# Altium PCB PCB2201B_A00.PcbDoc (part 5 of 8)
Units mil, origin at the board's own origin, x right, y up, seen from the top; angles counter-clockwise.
Board outline 4523.63 x 2358.23 mil, 6 copper layers (Top Layer, Signal Layer 2, Signal Layer 3, Signal Layer 4, Signal Layer 5, Bottom Layer), stack 61.221 mil thick; 383 components, 308 nets, 1386 pads, 1147 vias.
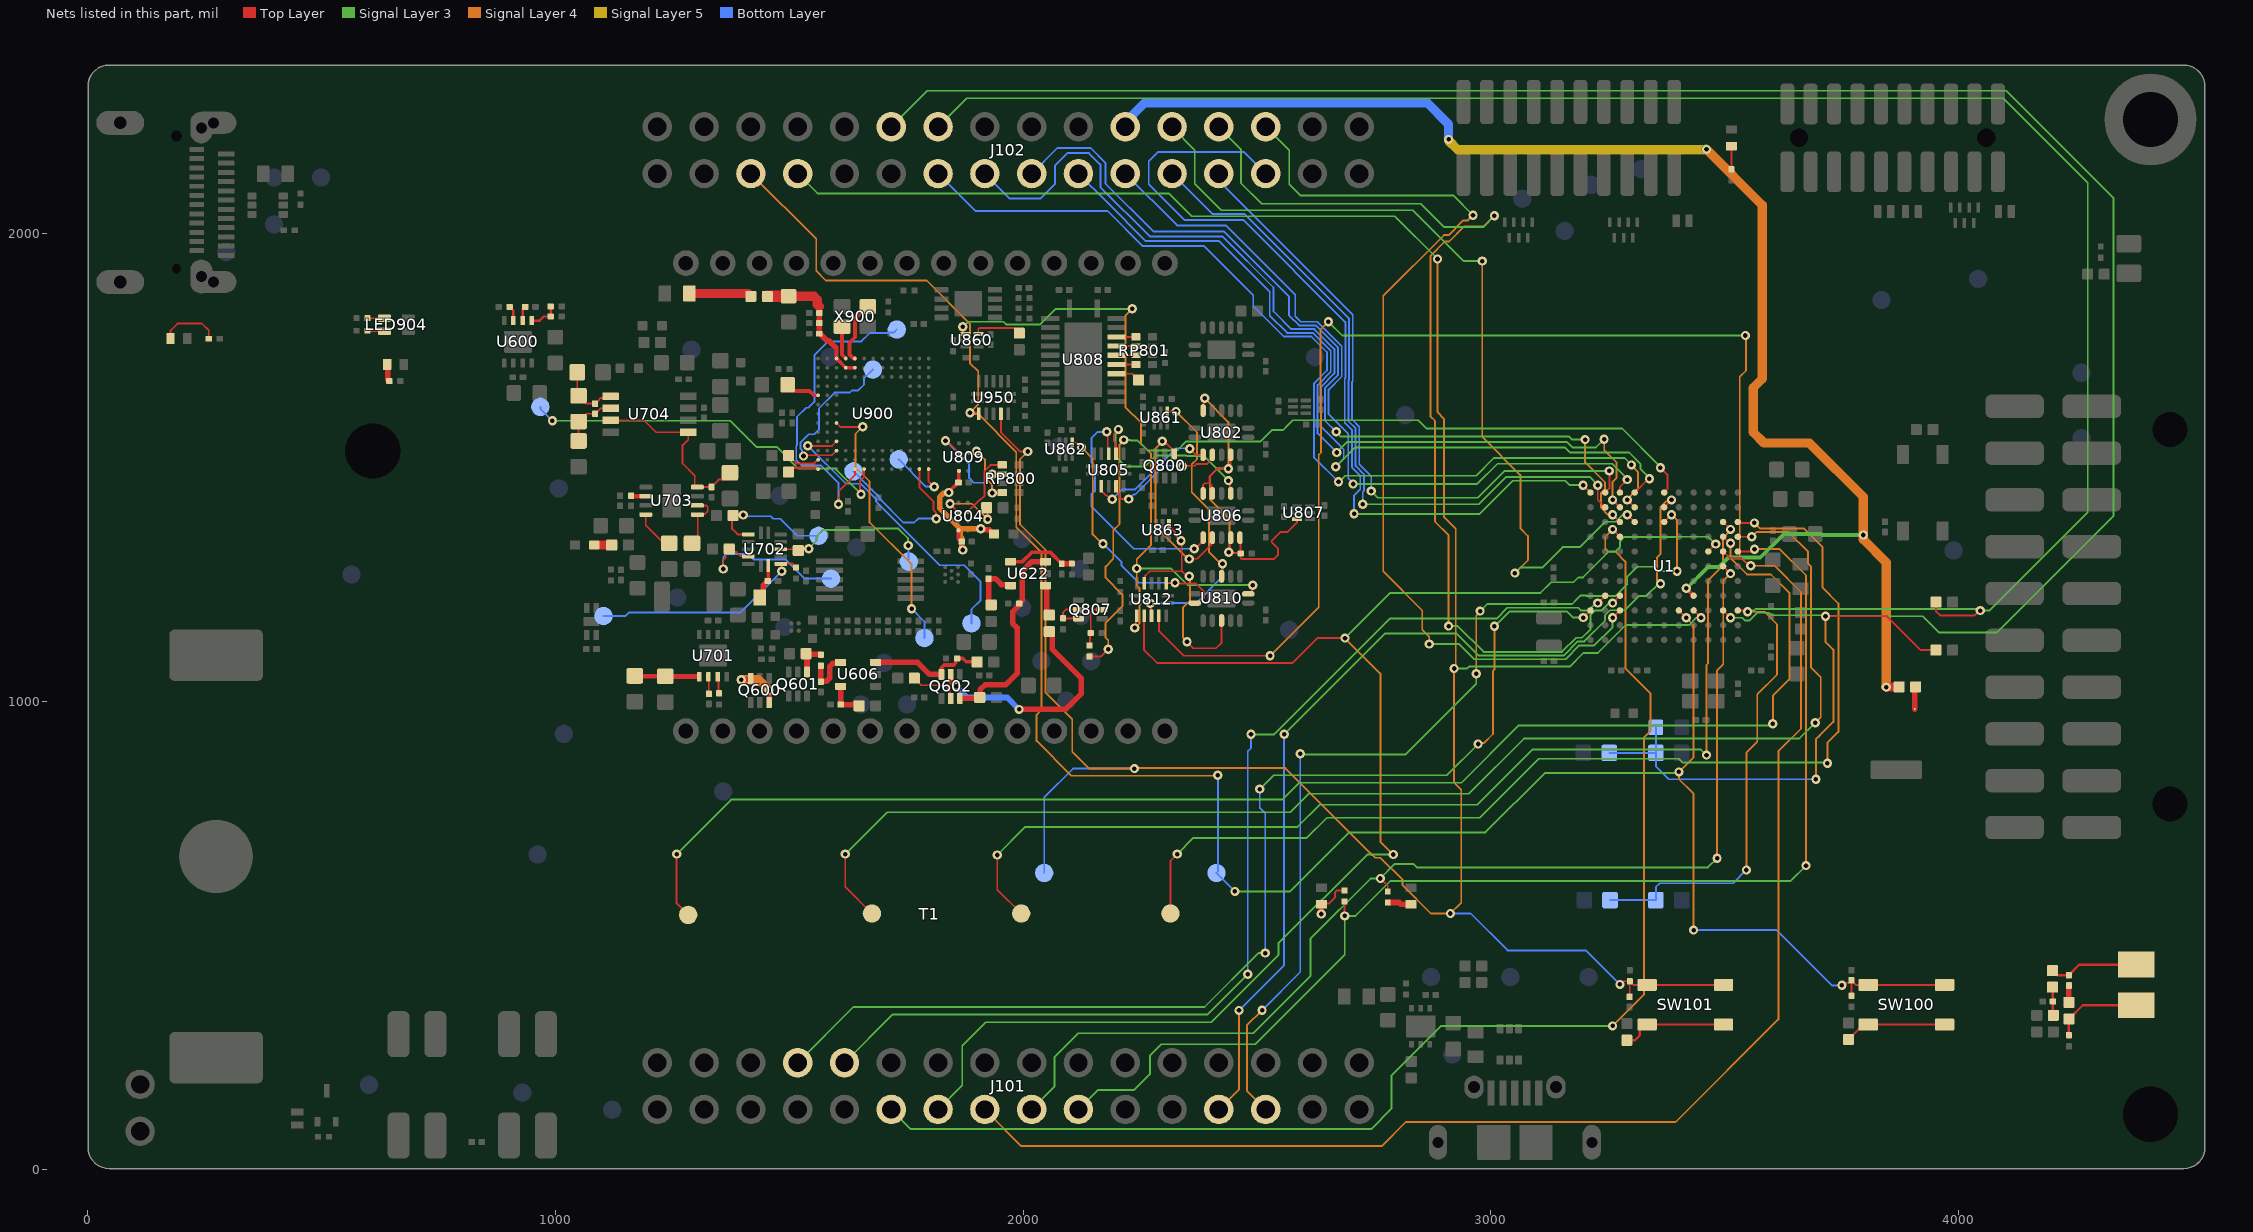
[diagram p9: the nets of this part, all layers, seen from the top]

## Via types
v1: diameter 19.68, hole 9.84, Top Layer to Bottom Layer, tented both sides, 768 vias
v2: diameter 20, hole 9.84, Top Layer to Bottom Layer, tented both sides, 379 vias

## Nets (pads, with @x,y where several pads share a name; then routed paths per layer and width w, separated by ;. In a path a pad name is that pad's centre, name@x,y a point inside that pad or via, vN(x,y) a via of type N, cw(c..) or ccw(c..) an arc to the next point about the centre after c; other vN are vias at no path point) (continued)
MCU_PB9: C102.1 J102.5 R100.1 SW100.3 SW100.4 TPJ652.1 U1.J7 U950.8 | length 4733
  Top Layer w3.94: v2(1886.66,1617.66) 1903.54,1617.66 1905.51,1615.69 U950.8@1905.51,1614.76 ; U1.J7@3401.57,1194.88 v1(3417.35,1179.09) ; v1(3750,393.7) 3754.26,393.7 3759.89,399.33 3766.1,399.33 C102.1@3770.43,403.66 ; C102.1@3770.36,404.52 C102.1@3770.43,404.45 C102.1@3770.43,403.66 ; R100.1@3770.43,371.46 C102.1@3770.43,403.66 ; SW100.3@3969.49,394.6 SW100.4@3806.1,394.6 3779.5,394.6 C102.1@3770.43,403.66
  Signal Layer 3 w3.94: J102.5@1418.5,2128.43 J102.5@1419.53,2128.43 ; v1(2452.76,594.49) 2570.87,594.49 2696.85,720.47 2988.19,720.47 3114.96,847.24 3398.97,847.24 v1(3401.53,849.81)
  Signal Layer 4 w3.94: J102.5@1418.5,2128.43 1558.07,1988.86 1558.07,1920.73 1578.89,1899.91 1794.4,1899.91 1886.63,1807.68 1886.63,1723.38 1904.29,1705.73 1904.29,1635.28 v2(1886.66,1617.66) ; v2@1885.73,1616.73 1887.51,1614.95 1903.9,1614.95 1985.62,1533.23 1985.62,1372.64 2039.37,1318.9 2039.37,982.28 2028.9,971.81 2028.9,915.98 2103.35,841.54 2415.35,841.54 v1(2416.34,842.52) ; v1(3417.35,1179.09) 3432.66,1163.79 3432.66,879.99 3402.47,849.81 v1(3401.53,849.81) 3401.53,834.69 3433.07,803.15 v1(3433.07,511.81)
  Bottom Layer w3.94: v1(2416.34,842.52) 2416.34,636.81 TPJ652.1@2413.39,633.86 v1(2452.76,594.49) ; v1(3433.07,511.81) 3610.47,511.81 3728.58,393.7 v1(3750,393.7)
MCU_PB10: C103.1 J102.7 R101.1 SW101.3 SW101.4 TPJ653.1 U1.J8 U950.11 | length 6302.6
  Top Layer w3.94: U950.11@1952.76,1614.76 1952.76,1575.56 1993.87,1534.45 v2(2009.84,1534.45) ; v1(3275.59,395.67) 3278.44,395.67 3285.17,402.4 R101.1@3296.69,402.4 ; C103.1@3296.34,369.06 3296.52,369.23 3296.52,402.22 R101.1@3296.69,402.4 ; U1.J8@3433.07,1194.88 v1(3448.85,1179.09) ; SW101.3@3497.05,394.6 SW101.4@3333.66,394.6 3304.1,394.6 3296.69,402.01 R101.1@3296.69,402.4
  Signal Layer 3 w3.94: J102.7@1518.5,2128.43 1560.75,2086.18 2311.46,2086.18 2360.24,2037.4 2794.29,2037.4 v1(2885.83,1945.87) ; v1(2921.26,1070.87) 2949.26,1070.87 2953.19,1074.8 3168.31,1074.8 3197.41,1103.91 3228.61,1103.91 3288.49,1163.78 3423.69,1163.78 3439,1179.09 v1(3448.85,1179.09)
  Signal Layer 4 w3.94: v2(2009.84,1534.45) 1993.5,1518.11 1993.5,1378.77 2048.23,1324.04 2048.23,1019.46 2105.32,962.38 2105.32,892.72 2141.19,856.85 v1(2238.06,856.85) 2239.05,857.83 2560.78,857.83 2742.28,676.34 2752.28,666.34 2763.78,666.34 2811.02,619.09 2811.02,607.59 2871.37,547.24 v1(2913.39,547.24) 2936.57,570.43 2936.57,811.7 2921.26,827.02 v1(2921.26,1070.87) 2921.26,1075.13 2924.76,1078.63 2924.76,1369.37 2899.49,1394.65 2899.49,1604.61 2885.83,1618.27 v1(2885.83,1945.87)
  Bottom Layer w3.94: TPJ653.1@2045.28,633.86 2045.28,795.28 2106.85,856.85 v1(2238.06,856.85) ; v1(2913.39,547.24) 2956.69,547.24 3035.43,468.5 3202.76,468.5 v1(3275.59,395.67)
MCU_PB15: J101.11 U1.D3 | length 2864.4
  Top Layer w3.94: v1(3259.89,1368.1) U1.D3@3275.59,1352.36
  Signal Layer 3 w4: J101.11@1718.5,128.43 1760.31,86.61 2744.09,86.61 2787.4,129.92 2787.4,200.79 2893.7,307.09 v1(3259.84,307.09)
  Signal Layer 4 w3.94: v1(3259.89,1368.1) 3244.09,1352.3 3244.09,1326.77 3250.46,1320.41 3266.21,1320.41 3287.4,1299.21 3287.4,1070.87 3341.1,1017.17 3341.1,937.56 3326.77,923.23
  Signal Layer 4 w4: v1(3259.84,307.09) 3260.02,307.09 3326.77,373.84 3326.77,923.23
MCU_PC1: J101.8 U1.J1 | length 2460.5
  Top Layer w3.94: v1(3197.42,1179.67) U1.J1@3212.6,1194.88
  Signal Layer 3 w3.94: J101.8@1518.5,228.43 1637.52,347.44 2387.8,347.44 2502.95,462.6 v1(2517.72,462.6) ; v1(2505.91,812.99) 2535.43,842.52 2905.51,842.52 v1(2972.44,909.45) ; v1(3007.44,1161.16) 3008.02,1161.16 3039.77,1192.91 3162.16,1192.91 3175.41,1179.67 v1(3197.42,1179.67)
  Signal Layer 4 w3.94: v1(2972.44,909.45) 2974.36,911.37 2984.91,911.37 3004.37,930.83 3004.37,1065.83 3007.44,1068.9 v1(3007.44,1161.16)
  Bottom Layer w3.94: v1(2505.91,812.99) 2505.91,773.62 2517.72,761.81 v1(2517.72,462.6)
MCU_PC2: J101.10 U1.H2 | length 2340.6
  Top Layer w3.94: v1(3228.35,1210.59) U1.H2@3244.09,1226.38
  Signal Layer 3 w3.94: J101.10@1618.5,228.43 1721.77,331.69 2394.69,331.69 v1(2480.32,417.32) ; v1(2487.2,930.12) 2536.42,930.12 2783.9,1177.6 3012.03,1177.6 3035.22,1200.79 3186.29,1200.79 3192.1,1194.98 3203.77,1194.98 3204.34,1194.41 3207.93,1194.41 3224.12,1210.59 v1(3228.35,1210.59)
  Bottom Layer w3.94: v1(2480.32,417.32) 2480.32,893.7 2487.2,900.59 v1(2487.2,930.12)
MCU_PC8: T1.1 U1.D10 | length 3106.4
  Top Layer w3.94: v1@1260.83,675.27 1259.84,674.29 v1(1259.84,674.21) 1259.84,568.83 T1.1@1284.42,544.26 ; U1.D10@3496.06,1352.36 3510.83,1337.61 3511.8,1336.64 v1(3511.8,1338.58)
  Signal Layer 3 w3.94: v1(1259.84,674.21) 1376.24,790.61 2554.39,790.61 2590.55,826.77 2937.01,826.77 3059.49,949.25 3598.86,949.25 v1(3602.36,952.76)
  Signal Layer 4 w3.94: v1(3511.8,1338.58) 3511.8,1307.09 3547.24,1271.65 3598.43,1271.65 3637.8,1232.28 3637.8,1047.99 3602.36,1012.56 v1(3602.36,952.76)
MCU_PC9: T1.2 U1.D11 | length 2892.7
  Top Layer w3.94: v1(1620.08,674.21) 1620.08,604.33 T1.2@1677.17,547.24 ; U1.D11@3527.56,1352.36 v1(3557.08,1352.36)
  Signal Layer 3 w3.94: v1(1620.08,674.21) 1709.65,763.78 2570.87,763.78 2610.24,803.15 2952.76,803.15 3070.87,921.26 3659.17,921.26 3692.75,954.85 v1(3692.93,954.85)
  Signal Layer 4 w3.94: v1(3557.08,1352.36) 3566.92,1362.2 3635.63,1362.2 3677.6,1320.23 3677.6,1294.84 3683.55,1288.89 3683.55,1073.7 3704.72,1052.52 3704.72,966.82 3692.93,955.02 v1(3692.93,954.85)
MCU_PC10: T1.3 U1.C10 | length 2286
  Top Layer w3.94: v1(1944.88,672.24) 1944.88,598.43 T1.3@1996.06,547.24 ; U1.C10@3496.06,1383.86 v1(3511.85,1368.09)
  Signal Layer 3 w3.94: v1(1944.88,672.24) 2004.92,732.28 2586.61,732.28 2633.86,779.53 2970.27,779.53 3088.38,897.64 3448.82,897.64 v1(3460.63,885.83)
  Signal Layer 4 w3.94: v1(3460.63,885.83) 3460.63,1078.74 3464.16,1082.27 3464.16,1259.44 3496.06,1291.34 3496.06,1350.57 3511.85,1366.36 v1(3511.85,1368.09)
MCU_PC11: T1.4 U1.C11 | length 2299.7
  Top Layer w3.94: T1.4@2314.96,547.24 2314.96,659.45 v1(2329.72,674.21) ; U1.C11@3527.56,1383.86 3529.53,1381.89 v1(3562.99,1381.89)
  Signal Layer 3 w3.94: v1(2329.72,674.21) 2364.17,708.66 2606.3,708.66 2649.61,751.97 2976.38,751.97 3102.27,877.86 3401.38,877.86 3408.97,870.28 3716.89,870.28 v1(3719.06,868.11)
  Signal Layer 4 w3.94: v1(3562.99,1381.89) 3574.8,1370.08 3668.15,1370.08 3708.6,1329.63 3708.6,1243.52 3742.44,1209.69 3742.44,935.39 3718.91,911.85 3718.91,868.26 v1(3719.06,868.11)
MCU_PD3: C250.1 J102.12 R240.2 R241.1 R245.1 U1.J10 | length 5590.4
  Top Layer w3.94: U1.J10@3496.06,1194.88 v1(3511.85,1179.09) ; v1(3714.8,1182.62) 3846.04,1182.62 3918.43,1110.24 R241.1@3950.79,1110.24
  Signal Layer 3 w3.94: J102.12@1718.5,2228.43 1795.45,2305.37 4101.37,2305.37 4330.71,2076.04 4330.71,1397.64 4080.71,1147.64 3957.8,1147.64 3922.82,1182.62 v1(3714.8,1182.62) ; v1(3511.85,1179.09) 3537.44,1179.09 3543.31,1173.23 3552.03,1173.23 3568.85,1190.06 3593.41,1190.06 3598.93,1184.53 3713.03,1184.53 v1@3714.8,1182.76
  Signal Layer 4 w3.94: v1@3688.63,831.74 3690.94,829.43 3694.2,829.43 v1@3699.92,835.16 ; v1(3694.31,834.12) 3694.31,919.18 ; 3703.68,928.55 3694.31,919.18 ; v1(3714.8,1182.62) 3714.8,1128.19 3731.81,1111.18 3731.81,956.68 3694.31,919.18
  Bottom Layer w3.94: R240.2@3252.68,890.43 R245.1@3352.4,890.43 ; C250.1@3352.4,945 R245.1@3352.4,890.43 ; v1(3694.31,834.12) 3379.93,834.12 3352.4,861.65 R245.1@3352.4,890.43
MCU_PD4: J102.14 R242.1 R243.1 R244.2 U1.J11 | length 5183.4
  Top Layer w3.94: U1.J11@3527.56,1194.88 3545.51,1194.88 v1(3548.4,1191.99) ; R242.1@3950.79,1212.6 3950.79,1193.04 3959.65,1184.17 4033.4,1184.17 4043.67,1194.45 v1(4045.39,1194.45)
  Signal Layer 3 w3.94: J102.14@1818.5,2228.43 1879.45,2289.37 4095.1,2289.37 4275.15,2109.32 4275.15,1405.07 4064.53,1194.45 4041.13,1194.45 4037.65,1197.93 3565.59,1197.93 3562.66,1195 3551.41,1195 v1(3548.4,1191.99)
  Signal Layer 4 w3.94: v1(3545.79,640.28) 3545.79,890.79 3569.17,914.17 3569.17,1015.87 3611.22,1057.92 3611.22,1165.43 3584.66,1191.99 v1(3548.4,1191.99)
  Bottom Layer w3.94: R244.2@3254.45,575.79 R243.1@3352.4,575.79 ; R243.1@3352.32,575.71 R243.1@3352.4,575.79 ; v1(3545.79,640.28) 3517.44,611.93 3360.47,611.93 3352.4,603.86 R243.1@3352.4,575.79
MCU_PD8: J102.22 R246.1 U1.H8 | length 3190.2
  Top Layer w8: v1(3417.35,1242.09) U1.H8@3433.07,1226.38
  Top Layer w19.68: v1(3844.84,1031.1) 3871.65,1031.1 R246.1@3872.05,1031.5
  Signal Layer 3 w8: v1(3417.35,1242.09) 3418.25,1242.09 3463.95,1287.8 3487.54,1287.8 3507.5,1307.76 3575.48,1307.76 3625.98,1358.27 3705.07,1358.27 3707.32,1356.02 v1(3795.55,1356.02)
  Signal Layer 3 w19.68: v1@3459.66,2181.09 v1(3460.63,2180.12)
  Signal Layer 4 w19.68: v1(3460.63,2180.12) 3579.72,2061.02 3579.72,1690.16 3560.32,1670.75 3560.32,1575.76 3583.4,1552.68 3680.43,1552.68 3795.55,1437.56 v1(3795.55,1356.02) 3795.55,1346.73 3844.84,1297.44 v1(3844.84,1031.1)
  Signal Layer 5 w19.68: v1(2909.41,2201.46) 2909.41,2199.29 2929.29,2179.41 3459.92,2179.41 v1(3460.63,2180.12)
  Bottom Layer w19.68: J102.22@2218.5,2228.43 2218.5,2237.83 2260.2,2279.53 2863.94,2279.53 2909.41,2234.06 v1(2909.41,2201.46)
MCU_PD13: J102.24 U1.C4 | length 1861.2
  Top Layer w3.94: v1(3291.35,1399.59) U1.C4@3307.09,1383.86
  Signal Layer 3 w3.94: J102.24@2318.5,2228.43 2318.5,2227.32 2367.13,2178.7 2367.13,2106.3 2423.23,2050.2 2832.68,2050.2 2941.44,1941.44 v1(2981.3,1941.44) ; v1(3051.18,1274.61) 3063.1,1286.53 3083.28,1286.53 3109.3,1286.53 3153.05,1330.27 3189.8,1330.27 3243.81,1384.28 3266.19,1384.28 3281.5,1399.59 v1(3291.35,1399.59)
  Signal Layer 4 w3.94: v1(2981.3,1941.44) 2981.3,1565.94 3062.99,1484.25 3062.99,1370.08 3079.18,1353.89 3079.18,1302.6 v1(3051.18,1274.61) ; v1@3291.35,1397.61 v1(3291.35,1399.59) v1@3291.35,1400.88
MCU_PD14: J102.26 U1.H3 | length 2166.6
  Top Layer w3.94: v1(3259.84,1210.63) U1.H3@3275.59,1226.38
  Signal Layer 3 w3.94: J102.26@2418.5,2228.43 2418.5,2227.32 2465.55,2180.28 2465.55,2108.27 2509.84,2063.98 2850.39,2063.98 2900.15,2014.22 2983.27,2014.22 v1(3007.44,2038.39) ; v1(2909.45,1161.42) 2929.13,1161.42 2984.25,1106.3 3151.57,1106.3 3181.79,1136.51 3194.59,1136.51 3213.04,1154.97 3213.04,1185.44 3222.01,1194.41 3235.24,1194.41 3251.46,1210.63 v1(3259.84,1210.63)
  Signal Layer 4 w3.94: v1(2909.45,1161.42) 2909.45,1355.32 2880.35,1384.41 2880.35,1599.96 2870.52,1609.8 2870.52,1952.21 2901.58,1983.27 2910.43,1983.27 2942.91,2015.75 2984.8,2015.75 v1(3007.44,2038.39)
MCU_PD15: J102.28 U1.J3 | length 2087.8
  Top Layer w3.94: v1(3259.84,1179.13) U1.J3@3275.59,1194.88
  Signal Layer 3 w3.94: J102.28@2518.5,2228.43 2568.9,2178.03 2568.9,2105.32 2592.52,2081.69 2919.29,2081.69 v1(2961.61,2039.37) ; v1(2868.31,1122.87) 2931.99,1122.87 2964.32,1090.55 3159.45,1090.55 3188.98,1120.08 3220.49,1120.08 3259.84,1159.43 v1(3259.84,1179.13)
  Signal Layer 4 w3.94: v1(2868.31,1122.87) 2867.96,1123.22 2867.96,1138.62 2853.07,1153.51 2853.07,1194.8 2769.68,1278.19 2769.68,1867.13 2899.61,1997.05 2909.45,1997.05 2940.94,2028.54 2950.79,2028.54 v1(2961.61,2039.37)
MCU_PE0: J101.13 U1.E9 U812.2 | length 3220.4
  Top Layer w3.94: U812.2@2258.86,1183.66 2258.86,1110.24 2286.36,1082.74 2576.12,1082.74 2629.21,1135.83 2685.04,1135.83 v1@2686.02,1134.84 ; U1.E9@3464.57,1320.87 3464.62,1320.87 v1(3480.35,1336.59)
  Signal Layer 3 w3.94: J101.13@1818.5,128.43 1870.08,180 1870.08,264.76 1920.28,314.96 2402.58,314.96 2545.82,458.2 2545.82,483.26 2735.79,673.23 2760.84,673.23 v1(2791.34,673.23) ; v1(2687.99,1135.83) 2784.45,1232.28 3105.82,1232.28 3128.57,1255.03 3176.42,1255.03 3186.7,1265.31 3196.41,1265.31 3251.97,1320.87 3265.77,1320.87 3276.04,1331.13 3276.04,1342.94 3285.01,1351.91 3393.24,1351.91 3393.7,1352.36 3464.58,1352.36 v1(3480.35,1336.59)
  Signal Layer 4 w3.94: v1(2687.99,1135.83) 2763.78,1060.04 2763.78,700.79 v1(2791.34,673.23)
MCU_PE1: J101.15 U1.E10 U812.4 | length 5447.7
  Top Layer w3.94: U812.4@2290.35,1183.66 2290.35,1151.57 2343.88,1098.05 2526.2,1098.05 v1@2526.57,1098.43 ; U1.E10@3496.06,1320.87 3509.82,1307.09 3535.42,1307.09 3552.09,1290.42 v1(3555.29,1290.42)
  Signal Layer 3 w3.94: v1(2652.56,1812.01) 2682.09,1782.48 v1(3543.74,1782.48)
  Signal Layer 4 w3.94: J101.15@1918.5,128.43 1996.61,50.32 2766.61,50.32 2817.95,101.65 3394.96,101.65 3614.17,320.87 3614.17,893.7 3662.51,942.04 3662.51,1234.14 3606.24,1290.42 v1(3555.29,1290.42) 3552.09,1290.42 3531.5,1311.01 3531.5,1693.9 3545.28,1707.68 3545.28,1782.48 v1(3543.74,1782.48) ; v1(2527.94,1098.05) 2528.28,1098.05 2631.89,1201.65 2631.89,1527.42 2636.82,1532.35 2636.82,1621.53 2635.51,1622.83 2635.51,1794.96 v1(2652.56,1812.01)
MCU_PE2: J101.17 R106.2 U1.F10 | length 2453.8
  Top Layer w3.94: v1(2763.78,622.05) 2779.53,606.3 R106.2@2779.53,594.49 ; U1.F10@3496.06,1289.37 3496.06,1289.31 3511.75,1273.62 v1(3511.81,1273.62)
  Signal Layer 3 w3.94: J101.17@2018.5,128.43 2066.93,176.85 2066.93,240.16 2118.11,291.34 2492.09,291.34 2614.25,413.5 2614.25,493.58 2742.72,622.05 v1(2763.78,622.05) 2794.84,653.11 2834.1,653.11 2841.53,645.67 3463.58,645.67 v1(3483.27,665.35)
  Signal Layer 4 w3.94: v1(3483.27,665.35) 3483.27,1066.93 3496.52,1080.18 3496.52,1258.33 v1(3511.81,1273.62)
MCU_PE3: J101.19 R107.2 U1.E11 | length 2665.9
  Top Layer w3.94: R107.2@2687.01,572.83 2687.28,572.56 2687.28,542.41 v1(2687.56,542.14) ; U1.E11@3527.56,1320.87 3561.02,1320.87 3563.17,1323.01 v1(3563.17,1325.85)
  Signal Layer 3 w3.94: J101.19@2118.5,128.43 2160.43,170.35 2237.28,170.35 2271.65,204.72 2271.65,244.09 2295.28,267.72 2496.06,267.72 2687.56,459.22 v1(2687.56,542.14) 2710.47,542.14 2785.35,617.02 3640.64,617.02 v1(3673.23,649.61)
  Signal Layer 4 w3.94: v1(3563.17,1325.85) 3617.06,1325.85 3673.23,1269.69 v1(3673.23,649.61)
MCU_PE8: J102.13 U1.B4 | length 2075.2
  Top Layer w3.94: v1@3294.12,1428.3 U1.B4@3307.09,1415.35
  Signal Layer 3 w3.94: v1(2674.13,1469.76) 2675.35,1469.76 2688.46,1482.88 2968.22,1482.88 3006.01,1520.67 3285.43,1520.67 v1(3300.2,1505.91)
  Signal Layer 4 w3.94: v1(3291.35,1431.09) 3291.35,1432.65 3314.53,1455.84 3314.53,1490.58 3300.2,1504.92 v1(3300.2,1505.91)
  Bottom Layer w3.94: J102.13@1818.5,2128.43 1898.17,2048.76 2180.57,2048.76 2255.91,1973.43 2387.32,1973.43 2492.13,1868.62 2492.13,1845.47 2557.35,1780.24 2616.18,1780.24 2649.61,1746.82 2649.61,1707.87 2621.5,1679.76 2621.5,1522.4 v1(2674.13,1469.76)
MCU_PE9: J102.15 U1.A4 | length 2130.7
  Top Layer w3.94: U1.A4@3307.09,1446.85 3314.62,1454.42 ; U1.A4@3307.1,1446.85 3336.63,1476.38 v1(3338.58,1476.38)
  Signal Layer 3 w3.94: v1(2668.46,1502.01) 2709.21,1542.76 3158.5,1542.76 3168.53,1532.73 3295.03,1532.73 3319.33,1508.42 3319.33,1497.6 3338.58,1478.35 v1(3338.58,1476.38)
  Bottom Layer w3.94: J102.15@1918.5,2128.43 1972.08,2074.85 2036.46,2074.85 2068.5,2106.89 2068.5,2146.26 2094.49,2172.24 2140.75,2172.24 2165.35,2147.64 2165.35,2099.41 2270.67,1994.09 2426.18,1994.09 2535.29,1884.98 2535.29,1833.8 2573.1,1795.99 2622.71,1795.99 2665.35,1753.34 2665.35,1701.35 2637.25,1673.24 2637.25,1587.04 2676.5,1547.79 2676.58,1547.79 2685.55,1538.82 2685.55,1519.09 v1(2668.46,1502.01)
MCU_PE10: J102.17 U1.C3 | length 1863.8
  Top Layer w3.94: v1(3259.85,1399.59) U1.C3@3275.59,1383.86
  Signal Layer 3 w3.94: v1(2669.17,1576.77) 2679.45,1566.5 3167.36,1566.5 3173.82,1560.04 v1(3201.22,1560.04)
  Signal Layer 4 w3.94: v1(3201.22,1560.04) 3201.22,1511.37 3243.66,1468.94 3243.66,1454.72 3235.24,1446.3 3235.24,1414.36 3250,1399.59 v1(3259.85,1399.59)
  Bottom Layer w3.94: J102.17@2018.5,2128.43 2073.15,2183.07 2144.69,2183.07 2176.18,2151.57 2176.18,2107.28 2278.54,2004.92 2429.13,2004.92 2568.74,1865.31 2568.74,1824.96 2589.83,1803.87 2625.97,1803.87 2673.23,1756.6 2673.23,1698.08 2645.12,1669.98 2645.12,1600.82 v1(2669.17,1576.77)
MCU_PE11: J102.19 U1.B3 | length 1731.2
  Top Layer w3.94: v1(3259.86,1431.15) U1.B3@3275.59,1415.35
  Signal Layer 3 w3.94: v1(2670.24,1532.48) 2692.91,1555.16 3161.69,1555.16 3173.54,1543.31 3224.41,1543.31 v1(3241.68,1560.57)
  Signal Layer 4 w3.94: v1(3241.68,1560.57) 3242.13,1560.57 3242.13,1537.26 3268.26,1511.12 3268.26,1484.1 3268.16,1484 3268.16,1477.81 3259.86,1469.51 v1(3259.86,1431.15)
  Bottom Layer w3.94: J102.19@2118.5,2128.43 2178.74,2068.19 2262.68,1984.25 2419.29,1984.25 2527.42,1876.13 2527.42,1824.95 2564.24,1788.12 2619.44,1788.12 2657.48,1750.08 2657.48,1704.61 2629.37,1676.5 2629.37,1573.34 v1(2670.24,1532.48)
MCU_PE12: J102.21 U1.A3 | length 1623.5
  Top Layer w3.94: U1.A3@3275.59,1446.85 3275.59,1458.64 v1(3291.35,1474.39)
  Signal Layer 3 w3.94: v1(2705.32,1465.16) 2737.62,1465.16 2737.75,1465.29 2970.84,1465.29 3013.97,1508.42 3259.29,1508.42 3291.35,1476.37 v1(3291.35,1474.39)
  Bottom Layer w3.94: J102.21@2218.5,2128.43 2329.21,2017.72 2433.07,2017.72 2581.69,1869.09 2581.69,1823.14 2593.1,1811.74 2629.23,1811.74 2681.1,1759.87 2681.1,1694.82 2653,1666.72 2653,1614.6 2694.99,1572.61 2694.99,1477.11 2705.32,1466.78 v1(2705.32,1465.16)
MCU_PE13: J102.23 U1.B2 | length 1506.2
  Top Layer w3.94: v1(3228.35,1462.6) 3228.35,1431.06 U1.B2@3244.09,1415.35
  Signal Layer 3 w3.94: v1(2725.87,1421.93) 2973.9,1421.93 3032.28,1480.32 3210.63,1480.32 v1(3228.35,1462.6)
  Bottom Layer w3.94: J102.23@2318.5,2128.43 2404.61,2042.32 2472.44,2042.32 2696.85,1817.91 2696.85,1688.3 2695.32,1686.77 2695.32,1599.7 2710.74,1584.28 2710.74,1503.74 2728.5,1485.98 2728.5,1450.63 2725.87,1448 v1(2725.87,1421.93)
MCU_PE14: J102.25 U1.A2 | length 1403
  Top Layer w3.94: U1.A2@3244.09,1446.85 3252.95,1455.71 v1(3252.95,1493.11)
  Signal Layer 3 w3.94: v1(2744.09,1449.98) 2758.32,1435.75 2972.06,1435.75 3029.42,1493.11 v1(3252.95,1493.11)
  Bottom Layer w3.94: J102.25@2418.5,2128.43 2418.5,2112.99 2704.72,1826.77 2704.72,1685.04 2703.19,1683.51 2703.19,1602.96 2718.61,1587.54 2718.61,1507 2744.09,1481.52 v1(2744.09,1449.98)
MCU_PE15: J102.27 U1.A1 | length 1842.7
  Top Layer w3.94: v1(3196.85,1462.6) U1.A1@3212.6,1446.85
  Signal Layer 3 w3.94: v1(2707.51,1401.3) 2975.95,1401.3 3046.65,1472 3158.74,1472 3168.15,1462.6 v1(3196.85,1462.6)
  Bottom Layer w3.94: J102.27@2518.5,2128.43 2472.72,2174.21 2288.31,2174.21 2268.7,2154.61 2268.7,2105.31 2344.49,2029.53 2470.47,2029.53 2688.98,1811.02 2688.98,1691.56 2687.44,1690.03 2687.44,1596.44 2702.87,1581.02 2702.87,1500.48 2720.63,1482.72 2720.63,1453.89 2707.51,1440.78 v1(2707.51,1401.3)
MCU_PF7: R841.2 U1.A6 | length 1834.4
  Top Layer w3.94: R841.2@2142.15,1096.27 2166.59,1096.27 v1(2182.09,1111.77) ; v1(3362.04,1500) 3376.97,1485.07 3376.97,1454.08 3370.08,1447.19 U1.A6@3370.08,1446.85
  Signal Layer 3 w3.94: v1(2215.28,1559.39) 2228.77,1559.39 2230.37,1557.79 ; 2234.45,1557.79 2230.37,1557.79 ; v1(3362.04,1500) 3362.04,1501.7 3279.98,1583.76 2862.06,1583.76 2844.44,1601.38 2576.77,1601.38 2564.52,1589.13 2555.55,1580.16 2531.93,1580.16 2507.87,1556.1 2348.91,1556.1 2329.5,1536.7 2266.23,1536.7 2245.14,1557.79 2230.37,1557.79
  Signal Layer 4 w3.94: v1(2182.09,1111.77) 2182.09,1131.18 2176.44,1136.83 2176.44,1168.35 2212.32,1204.22 2212.32,1228.77 2176.46,1264.63 2176.46,1288.7 2192.66,1304.9 2192.66,1365.89 2206.41,1379.64 2206.41,1549.25 2215.28,1558.12 v1(2215.28,1559.39)
MCU_PF8: J101.25 U1.B6 | length 2075.2
  Top Layer w3.94: U1.B6@3370.08,1415.35 3377.62,1422.92 ; U1.B6@3370.11,1415.35 v1(3385.85,1431.09)
  Signal Layer 3 w3.94: v1@2558.72,930.76 2773.62,1145.67 2893.7,1145.67 2926.18,1145.67 2973.43,1098.43 3155.51,1098.43 3185.73,1128.64 3199.55,1128.64 3243.66,1172.75 3243.66,1184.6 3254.37,1195.32 3285.92,1195.32 3316.51,1225.91 3332.31,1225.91 3358.38,1251.97 v1(3362.2,1251.97)
  Signal Layer 4 w3.94: J101.25@2418.5,128.43 2461.61,171.54 v1(2461.61,340.11) ; v1(3362.2,1251.97) 3354.74,1259.44 3354.74,1307.57 3362.2,1315.04 3362.2,1415.97 3374.39,1428.15 3382.91,1428.15 v1(3385.85,1431.09)
  Bottom Layer w3.94: v1(2461.61,340.11) 2558.07,436.57 v1(2558.07,930.12)
MCU_PF9: J101.27 U1.C6 | length 2055.9
  Top Layer w3.94: U1.C6@3370.08,1383.86 3377.62,1391.42 ; U1.C6@3370.11,1383.86 v1(3385.85,1399.59)
  Signal Layer 3 w3.94: v1(2592.5,888.58) 2594.27,886.81 2816.93,886.81 2968.5,1038.39 v1(2968.5,1059.49) ; v1(2976.73,1193.39) 2992.01,1208.66 3173.23,1208.66 3183.07,1218.5 ; 3183.09,1218.49 3191.15,1226.55 3203.83,1226.55 3204.44,1225.94 3266.18,1225.94 3291.35,1251.11 3291.35,1266.74 3312.99,1288.39 3349.41,1288.39 3359.25,1278.54 v1(3397.64,1278.54)
  Signal Layer 4 w3.94: v1(2510.83,340.55) 2478.35,308.07 2478.35,168.58 J101.27@2518.5,128.43 ; v1(2968.5,1059.49) 2968.5,1183.21 2976.73,1191.43 v1(2976.73,1193.39) ; v1(3385.85,1399.59) 3397.64,1387.81 v1@3397.64,1277.56
  Bottom Layer w3.94: v1(2510.83,340.55) 2592.5,422.23 v1(2592.5,888.58)
N16768220: R104.1 SW100.1 SW100.2 | length 218.8
  Top Layer w5: R104.1@3764.06,277.8 3785.95,299.69 3795.84,299.69 SW100.2@3806.1,309.95 SW100.1@3969.49,309.95
N16768338: R105.1 SW101.1 SW101.2 | length 228.3
  Top Layer w5: R105.1@3290.32,276.38 3307.68,276.38 3317.95,286.65 3317.95,299.66 3328.24,309.95 SW101.2@3333.66,309.95 SW101.1@3497.05,309.95
N16769621: LED101.1 R107.1 | length 88.5
  Top Layer w3.94: LED101.1@2637.8,566.77 2639.43,568.4 2653.21,568.4 2666.81,582.01 2666.81,592.76 2670.51,596.46 R107.1@2687.01,596.46
  Top Layer w12: v1(2637.41,546.21) 2637.6,546.4 2637.6,566.58 LED101.1@2637.8,566.77
N16769748: LED100.1 R106.1 | length 50.9
  Top Layer w12: R106.1@2779.53,570.87 2803.83,570.87 2807.53,567.16 2828.34,567.16 LED100.1@2828.74,566.77
N16831167: R700.1 U701.7 | length 36.7
  Top Layer w3.94: U701.7@1347.44,1053.15 1348.92,1051.67 1348.92,1019.19 R700.1@1350.39,1017.72
N16831188: C705.1 U701.6 | length 36.8
  Top Layer w3.94: U701.6@1327.76,1053.15 1328.25,1052.66 1328.25,1017.22 C705.1@1328.74,1016.73
N16831199: R702.1 R703.2 U701.5 | length 139.5
  Top Layer w3.94: U701.5@1307.58,1052.66 U701.5@1308.07,1053.15
  Top Layer w10: R702.1@1170.26,1054.94 1170.7,1054.5 1235.11,1054.5 R703.2@1235.55,1054.06 1236,1053.6 1307.99,1053.6 1308.07,1053.52 U701.5@1308.07,1053.15
N16831281: R705.2 TP711.1 U702.11 | length 374.9
  Top Layer w3.94: R705.2@1372.17,1326.17 1378.9,1319.44 1387.58,1319.44 1396.32,1310.7 1412.33,1310.7 U702.11@1412.99,1310.04
  Top Layer w4: v2(1359.53,1283.53) 1359.53,1302.51 1364.72,1307.7 1364.72,1318.72 R705.2@1372.17,1326.17
  Bottom Layer w4: v2(1359.53,1283.53) 1359.53,1308.49 1366.26,1315.22 1412.91,1315.22 1424.55,1303.58 1493.15,1303.58 1533.94,1262.8 TP711.1@1589.57,1262.8
N16831285: R706.2 TP712.1 U702.8 | length 266
  Top Layer w3.94: v2(1402.5,1398.83) 1381.12,1398.83 R706.2@1380.04,1397.76 1378.35,1396.06 1378.35,1369.13 1390.2,1357.28 U702.8@1408.27,1357.28
  Bottom Layer w3.94: v2(1402.5,1398.83) 1405.22,1396.11 1460.59,1396.11 1465.78,1390.92 1481.2,1390.92 1517.79,1354.33 TP712.1@1562.99,1354.33
N16831289: R707.2 TP713.1 U702.3 | length 353.3
  Top Layer w3.94: U702.3@1482.68,1325.79 1516.82,1325.79 R707.2@1519.7,1322.91 1523.87,1327.09 v2(1542.19,1327.09)
  Signal Layer 3 w3.94: v2(1542.19,1327.09) 1558.68,1343.58 1558.68,1353 1572.09,1366.42 1679.64,1366.42 1683.02,1369.8 1733.77,1369.8 1754.16,1349.41 1754.16,1334.42 v1(1754.92,1333.66)
  Bottom Layer w3.94: v1@1755.41,1330.22 1755.41,1299.7 TP713.1@1755.91,1299.21
N16831309: R708.2 TP714.1 U702.1 | length 473.6
  Top Layer w3.94: v2(1484.25,1278.54) 1484.25,1292.72 U702.1@1482.68,1294.29 1483.66,1295.28 1506.38,1295.28 1510.35,1291.31 1510.74,1291.31 1515.07,1286.98 R708.2@1515.07,1286.59
  Bottom Layer w3.94: TP714.1@1103.35,1182.78 1150.3,1182.78 1158.2,1190.68 1396.39,1190.68 v2(1484.25,1278.54)
N16831821: C707.1 L702.2 U702.14 | length 75.8
  Top Layer w7.87: C707.1@1453.74,1258.86 1454.33,1258.86 1455.71,1260.24 U702.14@1455.71,1290.94
  Top Layer w11.81: L702.2@1437.4,1222.44 1444.69,1229.72 1444.69,1248.62 1453.54,1257.48 1453.54,1258.07 C707.1@1453.74,1258.27
N16846192: R808.1 U802.6 U802.12 U806.5 U806.6 U806.12 U806.13 U807.3 | length 876.7
  Top Layer w3.94: U806.6@2384.84,1444.88 2384.84,1463.58 2387.79,1466.54 2398.62,1466.54 ; U802.6@2384.84,1622.05 2386.35,1623.55 2386.35,1646.44 v2(2388.16,1648.26) ; U806.5@2404.53,1444.88 2403.02,1446.39 2403.02,1462.14 2398.62,1466.54 ; U806.12@2443.9,1350.39 2442.39,1348.89 2442.39,1321.34 v2(2439.95,1318.9) 2441.05,1317.8 2464.21,1317.8 2464.45,1318.03 2464.45,1349.53 U806.13@2463.58,1350.39 ; U802.12@2443.9,1527.56 2443.9,1507.3 2438.98,1502.38 v2(2438.98,1498.03) 2415.13,1498.03 2398.62,1481.52 2398.62,1466.54 ; R808.1@2465.32,1316.69 2465.32,1306.79 2467.62,1304.49 2535.79,1304.49 2545.2,1313.89 2545.2,1326.58 2531.38,1340.4 2531.38,1343.66 2550.41,1362.69 2565.34,1362.69 2585.24,1382.6 2585.24,1389.57 U807.3@2585.82,1390.14
  Signal Layer 4 w3.94: v2(2388.16,1648.26) 2438.98,1597.44 v2(2438.98,1498.03) 2415.13,1498.03 2398.9,1481.8 2398.9,1432.42 2440.94,1390.38 2440.94,1319.89 v2(2439.95,1318.9)
N16846231: C804.1 C810.1 L801.2 U804.A2 U809.A2 | length 335.3
  Top Layer w7.87: v2(1841.54,1446.85) 1841.54,1448.62 1861.42,1468.5 C810.1@1862.2,1468.5 1862.96,1469.26 1862.96,1492.88 U809.A2@1863.19,1493.11 ; U804.A2@1862.2,1366.14 1862.2,1347.76 1868.11,1341.85 C804.1@1868.9,1341.85 1869.91,1340.84 1869.91,1325.09 v2(1870.93,1324.07)
  Top Layer w11.81: v2(1909.55,1369.16) 1911.12,1367.59 1927.68,1367.59 1937.01,1358.27 L801.2@1937.99,1358.27
  Signal Layer 4 w11.81: v2(1841.54,1446.85) 1839.97,1445.28 1830.01,1445.28 1821.85,1437.12 1821.85,1413.45 1866.14,1369.16 ; v2(1870.93,1324.07) 1869.39,1325.61 1869.39,1349.21 1866.14,1352.46 1866.14,1360.81 1866.14,1369.16 ; v2(1909.55,1369.16) 1874.49,1369.16 1866.14,1369.16
N16846319: Q800.1 U806.10 | length 405.6
  Top Layer w3.94: v2(2297.24,1556.1) 2300.32,1553.03 2305.24,1553.03 2322.83,1535.43 Q800.1@2322.83,1529.53 ; v2(2355.31,1304.84) 2355.71,1305.24 2372.17,1305.24 2403.02,1336.09 2403.02,1348.89 U806.10@2404.53,1350.39
  Signal Layer 4 w3.94: v2(2297.24,1556.1) 2297.24,1554.9 2282.76,1540.41 2282.76,1374.72 2353.98,1303.5 v2(2355.31,1304.84)
N16846537: RP801.5 U808.21 | length 41.5
  Top Layer w3.94: U808.21@2199.61,1779.53 RP801.5@2241.14,1779.53
N16846539: RP801.6 U808.20 | length 41.5
  Top Layer w3.94: U808.20@2199.61,1759.84 RP801.6@2241.14,1759.84
N16846547: RP801.7 U808.19 | length 41.5
  Top Layer w3.94: U808.19@2199.61,1740.16 RP801.7@2241.14,1740.16
N16846551: RP801.8 U808.18 | length 41.5
  Top Layer w3.94: U808.18@2199.61,1720.47 RP801.8@2241.14,1720.47
N16846723: R805.1 U808.17 | length 53.1
  Top Layer w3.94: U808.17@2199.61,1700.79 2233.27,1700.79 R805.1@2247.05,1687.01
N16846896: RP800.8 U809.C1 | length 143
  Top Layer w3.94: U809.C1@1882.87,1532.48 1883.85,1533.46 1898.63,1533.46 v2@1899.61,1532.48 ; v2(1934.06,1445.87) 1954.72,1445.87 RP800.8@1955.71,1446.85
  Signal Layer 4 w3.94: v2(1900.59,1535.43) 1918.69,1517.33 1918.69,1479.14 1934.06,1463.78 v2(1934.06,1445.87)
N16846900: RP800.6 U809.C2 | length 222.7
  Top Layer w3.94: v2(1834.31,1557.7) v2(1834.31,1557.7) 1836.64,1557.65 1861.8,1532.48 U809.C2@1863.19,1532.48 ; v2(1934.16,1486.29) v2(1934.16,1486.29) 1955.67,1486.26 RP800.6@1955.71,1486.22
  Bottom Layer w3.94: v2(1834.31,1557.7) 1884.84,1507.18 1884.84,1500 ; 1884.82,1500 1884.82,1478.15 1895.17,1467.8 1915.67,1467.8 v2(1934.16,1486.29)
N16846924: RP800.5 U804.C1 | length 146.1
  Top Layer w3.94: U804.C1@1881.89,1405.51 1907.76,1431.38 1908.97,1431.38 1918.03,1440.44 1918.03,1441.65 1918.03,1492.83 1931.1,1505.91 RP800.5@1955.71,1505.91
N16847739: U805.10 U806.9 | length 529.1
  Top Layer w3.94: v2(2178.87,1576.56) 2178.93,1576.56 2181.1,1574.39 2181.1,1531.69 U805.10@2183.07,1529.72 ; v2(2366.14,1326.77) 2367.62,1326.77 2384.84,1344 U806.9@2384.84,1350.39
  Bottom Layer w3.94: v2(2178.87,1576.56) 2159.54,1576.56 2146.23,1563.25 2146.23,1511.19 2153.54,1503.88 2153.54,1450.79 2145.67,1442.91 2145.67,1417.41 2236.31,1326.77 v2(2366.14,1326.77)
N16847741: U805.9 U806.3 | length 430
  Top Layer w3.94: U805.9@2198.82,1529.72 2198.82,1552.17 2193.9,1557.09 2193.9,1571.85 v1(2203.74,1581.69) ; v2(2438.98,1472.44) 2438.98,1468.09 2442.5,1464.57 2442.5,1446.28 U806.3@2443.9,1444.88
  Signal Layer 3 w3.94: v1(2203.74,1581.69) 2203.74,1577.43 2197.83,1571.53 2197.83,1524.41 2220,1502.25 2260.29,1502.25 2284.19,1526.15 2348.91,1526.15 2349.89,1525.17 2386.47,1525.17 2438.98,1472.66 v2(2438.98,1472.44)
N16847743: U802.10 U805.4 | length 273
  Top Layer w3.94: U805.4@2198.82,1460.04 2200.79,1458.07 2200.79,1448.61 2206.59,1442.81 2206.59,1435.2 2208.89,1432.9 v2(2225.97,1432.9) ; v2(2340.55,1502.81) 2340.55,1503.94 2366.84,1503.94 2370.5,1507.59 2392.44,1507.59 2404.53,1519.68 U802.10@2404.53,1527.56
  Bottom Layer w3.94: v2(2225.97,1432.9) 2235.72,1442.65 2239.89,1442.65 2301.18,1503.94 2340.55,1503.94 v2(2340.55,1502.81)
N16847749: U802.9 U805.2 | length 285.3
  Top Layer w3.94: U805.2@2167.32,1460.04 2167.32,1450.59 2173.23,1444.69 2177.15,1440.75 2178.57,1440.75 2186.6,1432.72 v2(2190.94,1432.72) ; v2(2356.3,1540.63) 2369.37,1527.56 U802.9@2384.84,1527.56
  Bottom Layer w3.94: v2(2190.94,1432.72) 2211.26,1453.04 2239.14,1453.04 2327.73,1541.62 2355.31,1541.62 v2(2356.3,1540.63)
N16847975: R810.1 U804.C2 | length 145.6
  Top Layer w3.94: v2@1843.9,1423.03 1843.9,1422.24 1844.09,1422.24 1860.82,1405.51 U804.C2@1862.2,1405.51 ; R810.1@1922.24,1414.37 1924.21,1412.4 v2(1924.21,1389.76)
  Signal Layer 4 w3.94: v2@1843.9,1423.03 1890.95,1423.03 v2(1924.21,1389.76)
  other v2: 1843.87,1423.03
N16916520: U810.1 U812.1 U860.4 | length 1448.2
  Top Layer w3.94: v2(1871.17,1801.27) 1871.17,1787.76 1873.13,1785.79 U860.4@1876.93,1785.79 ; v2(2239.05,1157.48) 2241.14,1159.57 2241.14,1181.69 U812.1@2243.11,1183.66 ; U810.1@2481.3,1230.32 2485.54,1230.32 2489.17,1233.95 2489.17,1247.05 v2(2491.14,1249.02)
  Signal Layer 3 w3.94: v2(1871.17,1801.27) 1872.72,1801.27 1883.19,1811.74 1958.32,1811.74 1963.95,1806.1 2036.42,1806.1 2069.6,1839.29 v2(2233.27,1839.29) ; v2(2243.11,1284.45) 2316.71,1284.45 2352.14,1249.02 v2(2491.14,1249.02)
  Signal Layer 4 w3.94: v2(2233.27,1839.29) 2218.78,1824.8 2218.78,1629.15 2252.21,1595.73 2252.21,1550.72 2273.62,1529.31 2273.62,1334.98 2243.11,1304.47 v2(2243.11,1284.45) 2243.11,1248.03 2249.02,1242.13 2249.02,1167.45 v2(2239.05,1157.48)
N16916530: U810.4 U812.3 U861.4 | length 658
  Top Layer w3.94: v2(2271.65,1210.63) 2273.13,1209.15 2273.13,1185.14 U812.3@2274.61,1183.66 ; U861.4@2308.07,1620.08 2308.13,1620.14 v2(2326.83,1620.14) ; U810.4@2424.21,1267.72 2425.2,1268.7 2425.2,1293.31 v2(2426.18,1294.29)
  Signal Layer 4 w3.94: v2(2326.83,1620.14) 2371.77,1575.2 2371.77,1518.42 2360.52,1507.17 2360.52,1447.78 2397.36,1410.93 2397.36,1319.94 2423.01,1294.29 v2(2426.18,1294.29)
  Bottom Layer w3.94: v2(2271.65,1210.63) 2370.35,1210.63 2426.18,1266.46 v2(2426.18,1294.29)
N16916558: U810.11 U812.11 U863.4 | length 515.2
  Top Layer w3.94: U812.11@2258.86,1253.35 2260.83,1255.32 2260.83,1268.68 2262.8,1270.65 ; 2262.8,1270.67 2270.67,1278.54 2339.29,1278.54 ; U863.4@2312.01,1379.92 2312.01,1373.03 2313.98,1371.06 2315.96,1371.06 2325.14,1361.88 2325.14,1355.96 2339.29,1341.81 2339.29,1278.54 ; v2(2350.39,1127.67) 2350.5,1127.67 2364,1114.17 2412.4,1114.17 2424.21,1125.98 U810.11@2424.21,1173.23 ; v2(2355.31,1267.72) 2350.97,1267.72 2342.93,1275.76 2342.07,1275.76 2339.29,1278.54
  Signal Layer 4 w3.94: v2(2350.39,1127.67) 2350.39,1129.39 2341.77,1138.01 2341.77,1200.86 2357,1216.09 2357,1266.03 v2(2355.31,1267.72)
  other v2: 2337.6,1343.5
N16916616: U810.8 U812.8 U862.4 | length 569
  Top Layer w3.94: U862.4@2105.32,1553.15 2115.16,1553.15 v2(2125,1543.31) ; U812.8@2306.1,1253.35 2306.69,1253.94 v2(2324.8,1253.94) 2326.49,1252.25 2369.77,1252.25 2386.81,1235.21 2386.81,1222.44 2375,1210.63 U810.8@2367.13,1210.63
  Signal Layer 4 w3.94: v2(2125,1543.31) 2149.17,1519.14 2149.17,1438.65 2148.74,1438.22 2148.74,1357.46 2168.96,1337.24 v1(2170.98,1337.24)
  Bottom Layer w3.94: v1(2170.98,1337.24) 2210.52,1297.71 2210.52,1290.46 2247.05,1253.94 v2(2324.8,1253.94)
N16917071: R882.1 U860.3 | length 103.2
  Top Layer w3.94: U860.3@1904.49,1785.79 1904.49,1795.92 1906.79,1798.23 1981.09,1798.23 1991.91,1787.4 R882.1@1992.13,1787.4
N16922979: R601.1 R602.2 U600.5 | length 65.2
  Top Layer w5: U600.5@950.79,1813.98 966.91,1813.98 975.98,1823.05 R601.1@990.61,1823.05 990.61,1844.03 R602.2@990.16,1844.49
N16923003: R600.1 U600.7 | length 33.5
  Top Layer w5: R600.1@903.01,1843.72 903.41,1843.72 907.21,1839.92 907.21,1839.52 910.89,1835.84 910.89,1814.51 U600.7@911.42,1813.98
N16923019: C602.1 U600.6 | length 34
  Top Layer w5: U600.6@930.57,1814.19 930.57,1837.81 931.89,1839.13 931.89,1839.92 C602.1@935.48,1843.5 ; C602.1@936.48,1843.72 935.69,1843.72 C602.1@935.48,1843.5 ; C602.1@937.01,1843.5 C602.1@935.48,1843.5
N16923678: Q602.6 R674.1 R675.1 U606.3 | length 257.7
  Top Layer w7.87: Q602.6@1825.79,1058.07 1825.87,1058.15 1825.87,1072.37 1831.84,1078.35 1851.88,1078.35 1856.5,1082.96 1856.5,1090.16 1858.86,1092.52 1862.01,1092.52 1871.12,1092.52 1878.43,1085.21 1901.44,1085.21 R675.1@1902.05,1084.61
  Top Layer w11.81: U606.3@1685.04,1083.66 1774.61,1083.66 1800.2,1058.07 Q602.6@1825.79,1058.07
N16923728: Q601.4 R628.1 R672.2 | length 70.6
  Top Layer w11.81: R628.1@1536.42,1102.36 R628.1@1538.39,1100.39 ; Q601.4@1538.39,1062.99 R628.1@1538.39,1100.39 ; R672.2@1567.91,1100.39 1567.91,1100.79 1567.52,1101.18 1539.17,1101.18 R628.1@1538.39,1100.39
N16923751: Q602.3 R687.1 R688.1 U622.3 | length 435
  Top Layer w11.81: Q602.3@1865.16,1006.89 1905.51,1006.89 R687.1@1907.48,1008.86 1908.46,1009.84 1908.46,1025.59 1919.35,1036.47 1963.49,1036.47 1987.2,1060.19 1987.2,1157.92 1977.8,1167.32 1977.8,1191.87 1991.34,1205.41 1991.34,1209.25 1991.73,1209.65 R688.1@1992.13,1209.65 ; R688.1@1998.03,1215.16 1998.03,1278.54 2018.7,1299.21 U622.3@2048.23,1299.21
N16923761: Q602.5 R686.2 | length 492.3
  Top Layer w11.81: Q602.5@1845.47,1058.07 1845.47,1044.58 v1(1857.15,1032.91) ; v1(1991.7,983.45) 1991.88,983.27 2090.55,983.27 2124.02,1016.73 2124.02,1050.2 2062.01,1112.2 2062.01,1143.7 R686.2@2056.1,1149.61
  Bottom Layer w11.81: v1(1857.15,1032.91) 1881.2,1008.86 1966.29,1008.86 v1(1991.7,983.45)
N16923771: C653.1 R629.1 U622.4 | length 149.3
  Top Layer w7.87: U622.4@1973.42,1299.21 1999.02,1299.21 2018.7,1318.9 2058.86,1318.9 2082.97,1294.78 C653.1@2083.07,1294.78
  Top Layer w11.81: C653.1@2083.07,1294.78 2103.94,1294.78 2104.33,1295.18 R629.1@2104.33,1295.28
N16923807: R686.1 U622.1 | length 66.8
  Top Layer w11.81: U622.1@2048.23,1248.03 2049.21,1248.03 2051.18,1246.06 2051.18,1189.96 R686.1@2056.1,1185.04
N16923899: C652.1 R690.1 U622.5 | length 112.7
  Top Layer w11.81: R690.1@1932.09,1206.69 1926.57,1212.2 1926.57,1262.8 1940.94,1262.8 1953.74,1250 1971.46,1250 U622.5@1973.42,1248.03 U622.5@1972.44,1247.05
N16923917: C660.1 R681.1 U606.5 | length 79
  Top Layer w11.81: U606.5@1610.24,1032.48 C660.1@1610.24,994.09 1610.63,993.7 1647.05,993.7 R681.1@1649.61,991.14
N16923949: Q602.2 R679.2 | length 103.8
  Top Layer w3.94: R679.2@1767.72,1050.2 1782.88,1035.03 1831.11,1035.03 1843.84,1022.3 1843.84,1008.52 Q602.2@1845.47,1006.89
N16923963: C621.1 R672.1 U606.4 | length 106.1
  Top Layer w11.81: C621.1@1567.91,1042.32 C621.1@1567.91,1042.91 ; R672.1@1567.91,1074.8 C621.1@1567.91,1042.91 ; U606.4@1610.24,1083.66 1608.27,1081.69 1593.53,1081.69 1586.61,1074.77 1586.61,1050.42 1579.7,1043.5 1568.31,1043.5 1567.91,1043.11 C621.1@1567.91,1042.91
N16924927: Q600.3 Q600.6 | length 116.2
  Top Layer w11.81: v2(1398.19,1046.69) 1399.65,1048.15 1417.83,1048.15 Q600.6@1417.83,1049.61 ; Q600.3@1457.2,998.43 1457.2,1023.66 v1(1457.56,1024.02)
  Signal Layer 4 w19.68: v2(1398.19,1046.69) 1398.25,1046.63 1434.94,1046.63 v1(1457.56,1024.02)
N16934878: C900.1 U900.J13 | length 74.9
  Top Layer w7.87: C900.1@1497.05,1677.17 1497.09,1676.13 1508.86,1664.37 1512.8,1664.37 1513.47,1663.7 1543.48,1663.7 1552.66,1654.53 U900.J13@1562.01,1654.53
N16934900: C903.1 C904.1 C905.1 C906.1 R130.2 U900.M9 U900.M10 U900.N11 | length 306.4
  Top Layer w7.87: C906.1@1564.92,1830.47 1564.92,1848.92 ; 1601.38,1756.89 U900.N11@1601.38,1733.27 U900.M10@1621.06,1713.58 U900.M9@1640.75,1713.58
  Top Layer w11.81: C906.1@1564.92,1830.47 C905.1@1564.92,1808.86 C904.1@1564.92,1786.18 1565.71,1786.18 1580.73,1771.16 1585.14,1771.16 1599.41,1756.89
  Top Layer w19.68: C903.1@1499.02,1866.14 1553.15,1866.14 1560.4,1858.89 1560.4,1848.97 1564.86,1844.51
  Top Layer w25: R130.2@1453.74,1866.14 C903.1@1499.02,1866.14
N16936696: U900.N10 X900.1 | length 71.2
  Top Layer w7.87: X900.1@1613.19,1801.18 1613.19,1741.14 U900.N10@1621.06,1733.27
N16936699: U900.N9 X900.3 | length 134.6
  Top Layer w7.87: U900.N9@1640.75,1733.27 1637.77,1733.27 1629.37,1741.66 1629.37,1767.17 1640.75,1778.54 1640.75,1818.26 1666.98,1844.49 X900.3@1668.31,1844.49
N16939106: TPJ909.1 U900.C11 | length 360.3
  Top Layer w3.94: v2(1530.91,1524.98) 1532.5,1526.57 1591.54,1526.57 U900.C11@1601.38,1536.42
  Bottom Layer w3.94: v2(1530.91,1524.98) 1527.83,1528.06 1527.83,1537.51 1524.61,1540.74 1524.61,1554.16 1541.99,1571.54 1553.82,1571.54 1563.98,1581.69 1563.98,1626.97 1597.44,1660.43 1609.22,1660.43 1609.41,1660.63 1630.11,1660.63 1634.56,1665.07 1648.01,1665.07 1660.18,1677.25 1660.18,1690.69 TPJ909.1@1679.13,1709.65
N16939109: TPJ910.1 U900.D11 | length 656.1
  Top Layer w3.94: v2(1540.07,1547.15) 1539.77,1546.84 1540.35,1546.26 1591.54,1546.26 U900.D11@1601.38,1556.1
  Bottom Layer w3.94: v2(1540.07,1547.15) 1621.67,1465.55 1653.5,1465.55 1669.3,1449.75 1685.77,1433.28 1685.77,1427.88 1822.3,1291.34 1874.02,1291.34 1909.27,1256.08 1909.27,1216.36 1889.76,1196.85 TPJ910.1@1889.76,1167.32
N16939489: TPJ911.1 U900.F11 | length 578.8
  Top Layer w3.94: U900.F11@1601.38,1595.47 1609.7,1587.15 v2(1657.48,1587.15)
  Signal Layer 4 w3.94: v2(1657.48,1587.15) 1657.26,1587.37 1642.01,1572.13 1642.01,1500.7 1671.96,1470.75 1671.96,1383.15 1761.81,1293.31 v2(1761.81,1198.82)
  Bottom Layer w3.94: v2(1761.81,1198.82) 1789.37,1171.26 TPJ911.1@1789.37,1135.83
N16939638: TPJ900.1 U900.A2 | length 347.7
  Top Layer w3.94: U900.A2@1778.54,1497.05 1778.54,1457.93 1800.82,1435.65 1808.93,1427.54 1808.93,1409.57 1813.79,1404.72 1813.79,1391.73 v2(1814.4,1391.12)
  Bottom Layer w3.94: TPJ900.1@1638.06,1492.13 1664.16,1466.02 1677.17,1453.01 1693.64,1436.54 1693.64,1435.61 1693.64,1433.43 1744.3,1382.77 1767.61,1382.77 1775.96,1391.12 v2(1814.4,1391.12)
N16939640: TPJ901.1 U900.A1 | length 141.4
  Top Layer w3.94: U900.A1@1798.23,1494.73 1798.23,1470.33 1808.41,1460.15 1808.41,1459.54 v2(1809.94,1459.54)
  Bottom Layer w3.94: TPJ901.1@1734.25,1517.72 1792.5,1459.47 1807.27,1459.47 1808.07,1458.66 1808.95,1459.54 v2(1809.94,1459.54)
N16940103: TPJ908.1 U900.A9 | length 694.1
  Top Layer w3.94: v2@1605.54,1422.37 1605.76,1422.59 1605.76,1435.66 1607.37,1437.28 1607.37,1450.35 ; 1612.59,1455.56 1607.37,1450.35 ; U900.A9@1640.75,1497.05 1640.75,1483.72 1607.37,1450.35
  Bottom Layer w3.94: v2(1605.76,1422.15) 1605.76,1466.65 1567.56,1504.84 1526.65,1504.84 1515.32,1516.17 1515.32,1547.3 1516.73,1548.71 1516.73,1608.29 1536.4,1627.95 1541.48,1627.95 1554.13,1640.6 1554.13,1740.16 1583.66,1769.69 1654.53,1769.69 1672.63,1787.78 1710.29,1787.78 1711,1788.5 1723.54,1788.5 TPJ908.1@1730.31,1795.28
N16942491: R902.2 U900.B13 | length 73
  Top Layer w4.72: R902.2@1499.02,1525.59 1515.49,1509.12 1554.03,1509.12 1561.64,1516.73 U900.B13@1562.01,1516.73
N16942503: R904.2 U900.A13 | length 67.6
  Top Layer w4.72: R904.2@1499.02,1491.14 1507.55,1499.67 1558.53,1499.67 1561.16,1497.05 U900.A13@1562.01,1497.05
N16943456: TPJ902.1 U900.A8 | length 823.3
  Top Layer w3.94: v2(1653.83,1443.3) 1651.58,1445.55 1651.58,1471.46 1660.43,1480.32 U900.A8@1660.43,1497.05
  Signal Layer 3 w3.94: v1(994.25,1600.16) 1374.25,1600.16 1430.12,1544.29 1473.43,1544.29 1519.69,1498.03 1599.14,1498.03 v2@1653.83,1443.35
  Bottom Layer w3.94: TPJ902.1@968.5,1629.92 968.5,1625.91 v1(994.25,1600.16)
N16944010: LED903.2 R912.2 | length 29
  Top Layer w12: LED903.2@642.72,1712.6 642.72,1687.99 644.98,1685.73 644.98,1685.34 645.28,1685.04 R912.2@645.67,1685.04
N16966205: LED904.2 R920.2 | length 36.5
  Top Layer w3.94: R920.2@599.29,1819.49 599.88,1818.9 607.28,1818.9 607.68,1819.29 LED904.2@635.39,1819.29
N16966207: LED904.1 R919.2 | length 36.4
  Top Layer w3.94: R919.2@599.29,1792.56 599.53,1792.32 608.27,1792.32 608.86,1791.73 LED904.1@635.39,1791.73
N16966211: LED901.1 R903.2 | length 128.1
  Top Layer w3.94: LED901.1@178.15,1776.59 178.15,1792.83 193.39,1808.07 245.08,1808.07 259.84,1793.31 R903.2@259.84,1775.59
N16966215: LED900.1 R900.2 | length 49.2
  Top Layer w3.94: R900.2@3513.78,2137.8 LED900.1@3513.78,2187.01
N16996446: Q807.5 Q807.6 R838.1 | length 80.5
  Top Layer w3.94: Q807.6@2118.11,1177.17 2117.62,1177.66 2086.12,1177.66 R838.1@2085.63,1178.15 2085.63,1190.75 2091.73,1196.85 Q807.5@2118.11,1196.85
N16997087: Q807.2 R839.2 R841.1 | length 98
  Top Layer w3.94: R841.1@2142.15,1119.89 2143.42,1121.16 2143.42,1145.39 R839.2@2144.68,1146.65 2144.68,1188.98 2152.56,1196.85 Q807.2@2169.29,1196.85
N17012885: L900.2 R130.1 | length 131
  Top Layer w19.68: L900.2@1287.01,1872.05 1412.4,1872.05 R130.1@1416.34,1868.11
N17206837: C198.1 L100.1 R197.2 | length 193.1
  Top Layer w5: R197.2@4199.88,425.2 4209.96,415.12 C198.1@4234.96,415.12 4234.96,415.91 4257.05,437.99 L100.1@4378.83,437.99
N17206841: L100.2 R195.1 R196.2 | length 190.7
  Top Layer w5: R196.2@4234.96,287.13 4234.96,321.68 R195.1@4235.13,321.85 4264.65,351.38 L100.2@4378.83,351.38
N17206845: C198.2 R195.2 | length 36.3
  Top Layer w11.81: C198.2@4234.96,393.46 4235.04,393.38 4235.04,357.37 R195.2@4235.13,357.28
N17206847: C199.1 R197.1 R198.2 | length 60.8
  Top Layer w5: R197.1@4199.88,389.76 4200.79,388.86 C199.1@4200.79,359.29 4200.79,330.6 R198.2@4201.66,329.72
N17234269: C200.1 R246.2 | length 48.1
  Top Layer w11.81: C200.1@3905.51,984.25 3905.51,1029.53 R246.2@3907.48,1031.5
N17262372: C729.1 R718.2 U703.4 U704.3 U704.5 | length 391
  Top Layer w3.94: U704.3@1118.88,1601.38 1190.04,1601.38 1215.63,1575.79 U704.5@1284.67,1575.79 1284.67,1560.1 1272.64,1548.07 1272.64,1508.86 1298.54,1482.95 1298.54,1461.58 1301.46,1458.66 U703.4@1304.13,1458.66 C729.1@1334.65,1458.66 1334.65,1459.45 1349.61,1474.41 R718.2@1375,1474.41
N17262509: R709.1 U703.1 U703.2 | length 124.1
  Top Layer w3.94: R709.1@1292.6,1338.58 1305,1350.98 1305,1398.75 U703.1@1304.13,1399.61 1305.64,1401.11 1320.37,1401.11 1326.26,1407.01 1326.26,1415.76 1322.73,1419.29 U703.2@1304.13,1419.29
N17262517: C710.2 U703.6 | length 31.9
  Top Layer w9.84: C710.2@1162.4,1439.96 1163.39,1438.98 U703.6@1193.9,1438.98
N17262549: R710.1 U703.8 | length 88.3
  Top Layer w3.94: U703.8@1193.9,1399.61 1193.9,1376.97 R710.1@1232.28,1338.58
  Top Layer w5: R710.1@1232.28,1338.58 R710.1@1243.7,1338.58
N17262561: L700.2 R717.1 | length 37.4
  Top Layer w19.68: L700.2@1083.66,1334.65 R717.1@1121.06,1334.65
N17262689: C766.1 R765.1 R767.2 U704.2 | length 121.8
  Top Layer w3.94: R767.2@1050.2,1557.09 R765.1@1050.2,1598.43 1066.93,1615.16 C766.1@1085.63,1615.16 1097.44,1626.97 U704.2@1118.88,1626.97
N17262695: C766.2 R764.1 R765.2 U704.1 | length 134
  Top Layer w3.94: R764.1@1047.24,1703.74 1047.24,1656.5 R765.2@1050.2,1653.54 1066.93,1636.81 C766.2@1085.63,1636.81 1085.63,1637.6 1089.96,1641.93 1090.75,1641.93 1097.78,1648.96 1115.28,1648.96 U704.1@1118.88,1652.56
